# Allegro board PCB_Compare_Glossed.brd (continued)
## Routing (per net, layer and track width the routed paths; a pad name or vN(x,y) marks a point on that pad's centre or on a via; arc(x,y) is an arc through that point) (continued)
RA8: length 166.3
  TOP w0.127: v1(106.17,77.39) 106.17,82.17 106.68,82.68 U16.28 ; U11.28 106.68,105.33 107.31,104.7 107.31,99.06 106.68,98.42 U17.28 v1(106.68,94.72) ; 59.18,87 v1(59.72,86.46) ; v1(81.91,81.48) U14.28 81.91,85.85 81.28,86.49 81.28,89.97 81.91,90.6 U13.28 81.91,98.37 82.55,99.01 82.55,105.66 81.91,106.3 U15.28 ; U12.28 106.68,69.52 v1(107.7,68.5) ; U10.28 81.91,67.26 v1(81.41,66.75)
  INNER_1 w0.127: v1(107.7,68.5) 106.17,70.03 v1(106.17,77.39) 106.68,77.9 v1(106.68,94.72) ; v1(81.91,81.48) 81.91,67.26 v1(81.41,66.75)
  INNER_2 w0.127: v1(81.91,81.48) 82.63,80.77 83.44,80.77 83.69,80.52 83.69,80.01 82.93,79.25 61.14,79.25 57.94,82.45 57.94,85.42 58.45,85.93 59.18,85.93 v1(59.72,86.46) ; v1(81.41,66.75) 81.91,67.26 106.45,67.26 v1(107.7,68.5)
RA9: length 158.6
  TOP w0.127: U14.22 89.53,79.78 v1(90.3,79.02) ; U10.22 89.53,72.19 v1(88.27,73.46) ; U13.22 89.53,98.37 88.9,99.01 88.9,101.4 88.95,101.45 v1(88.95,102.31) 89.53,102.9 U15.22 89.53,111 89.66,111.12 114.17,111.12 114.3,111 U11.22 114.3,107.14 113.66,106.5 113.66,99.01 114.3,98.37 U17.22 114.3,94.69 113.66,94.06 113.66,86.31 114.3,85.67 U16.22 114.3,77.93 113.66,77.29 113.66,73.61 114.3,72.97 U12.22 ; U5.E8 v1(58.45,88.8)
  BOTTOM w0.127: v1(88.95,102.31) 89.1,102.16 89.1,80.21 v1(90.3,79.02) 90.3,75.49 v1(88.27,73.46) 68.1,73.46 58.95,82.6 58.95,88.29 v1(58.45,88.8)
RA10: length 147
  TOP w0.127: v1(91.31,66.75) 90.81,67.26 U10.21 90.81,73.1 91.44,73.74 91.44,76.07 91.31,76.2 91.31,80.39 90.81,80.9 U14.21 90.81,85.7 90.17,86.33 v1(90.17,89.41) 91.31,90.55 91.31,93.78 90.81,94.28 U13.21 90.81,98.63 91.44,99.26 91.44,104.72 90.81,105.36 U15.21 ; U5.E9 v1(59.72,88.8) ; v1(115.93,66.75) 115.57,67.11 U12.21 115.57,72.97 114.94,73.61 114.94,76.02 115.57,76.66 U16.21 115.57,85.67 114.94,86.31 114.94,90.5 115.57,91.14 U17.21 115.57,98.65 116.21,99.29 116.21,104.72 115.57,105.36 U11.21
  INNER_2 w0.127: v1(90.17,89.41) 88.57,87.81 60.71,87.81 v1(59.72,88.8)
  BOTTOM w0.127: v1(115.93,66.75) v1(91.31,66.75)
RA11: length 171.8
  TOP w0.127: U5.E10 v1(60.99,88.8) ; v1(91.82,79.27) 92.07,79.53 U14.20 92.07,85.67 91.44,86.31 91.44,88.77 91.57,88.9 91.57,90.88 92.07,91.39 U13.20 92.07,98.37 92.58,98.88 92.58,104.85 92.07,105.36 U15.20 ; U10.20 92.07,66.24 v1(91.82,65.99) ; U11.20 116.84,105.36 117.35,104.85 117.35,99.14 116.84,98.63 U17.20 116.84,91.39 117.35,90.88 117.35,86.18 116.84,85.67 U16.20 116.84,76.66 116.21,76.02 116.21,73.61 116.84,72.97 U12.20 v1(116.84,69.8)
  INNER_1 w0.127: v1(91.82,65.99) v1(91.82,79.27)
  INNER_2 w0.127: v1(91.82,65.99) 113.03,65.99 v1(116.84,69.8)
  BOTTOM w0.127: v1(60.99,88.8) 60.48,89.31 58.19,89.31 57.94,89.05 57.94,82.35 67.34,72.95 88.52,72.95 91.82,76.25 v1(91.82,79.27)
RA12: length 165.7
  TOP w0.127: v1(93.34,70.31) 93.34,72.77 92.71,73.41 92.71,81.51 93.34,82.14 93.34,85.93 93.85,86.44 93.85,90.68 93.34,91.19 93.34,97.16 92.84,97.66 92.84,107.92 93.34,108.43 93.34,109.86 ; U11.19 118.11,108.56 117.6,108.05 117.6,98.88 118.11,98.37 U17.19 118.11,94.18 117.6,93.68 117.6,86.18 118.11,85.67 U16.19 118.11,82.83 117.47,82.19 117.47,73.61 118.11,72.97 U12.19 118.11,70.36 v1(117.63,69.88) ; U5.G2 v1(49.76,85.19)
  INNER_2 w0.127: v1(117.63,69.88) 116.18,71.32 94.36,71.32 v1(93.34,70.31) 88.67,74.98 50.65,74.98 49.12,76.5 49.12,80.04 51.54,82.45 51.54,83.41 v1(49.76,85.19)
RA13: length 154.7
  TOP w0.127: 50.29,87 v1(49.76,86.46) ; U15.18 94.62,108.43 95.25,107.8 95.25,99.01 94.62,98.37 U13.18 94.62,91.21 94.11,90.7 94.11,86.18 94.62,85.67 U14.18 94.62,81.38 v1(93.34,80.11) 93.98,79.48 93.98,73.61 94.62,72.97 U10.18 ; U12.18 119.38,72.97 118.75,73.61 118.75,79.91 v1(119.38,80.54) U16.18 119.38,85.67 118.75,86.31 118.75,88.77 118.87,88.9 118.87,95.43 119.38,95.94 U17.18 119.38,98.6 118.75,99.24 118.75,106.02 119.38,106.65 U11.18
  INNER_2 w0.127: v1(49.76,86.46) 51.79,84.43 51.79,83.67 52.04,83.41 57.15,83.41 57.68,82.88 57.68,82.3 60.99,78.99 83.82,78.99 84.94,80.11 v1(93.34,80.11) 118.95,80.11 v1(119.38,80.54)
RA14: length 164.5
  TOP w0.127: U10.15 94.62,65.2 95.25,65.84 95.25,72.85 94.62,73.48 U14.15 94.62,79.12 95.25,79.76 95.25,85.55 94.62,86.18 U13.15 94.62,90.22 v1(95.88,91.49) ; U12.15 119.38,63.45 120.01,64.08 120.01,72.85 119.38,73.48 U16.15 119.38,77.93 120.01,78.56 120.01,85.57 119.38,86.21 U17.15 119.38,91.9 120.01,92.53 120.01,98.37 119.38,99.01 U11.15 v1(119.38,104.14) ; U15.15 v1(94.62,104.01) ; U5.E2 v1(49.76,88.8)
  INNER_1 w0.127: v1(94.62,104.01) 94.74,104.14 v1(119.38,104.14)
  INNER_2 w0.127: v1(49.76,88.8) 50.52,89.56 51.26,89.56 53.04,91.34 53.04,91.57 53.57,92.1 95.28,92.1 v1(95.88,91.49)
  BOTTOM w0.127: v1(95.88,91.49) 94.62,92.76 v1(94.62,104.01)
RA15: length 163.7
  TOP w0.127: 93.34,100.33 v1(93.34,98.68) ; 93.34,87.63 93.34,86.69 v1(92.84,86.18) ; U11.14 118.11,98.96 118.75,98.32 118.75,96.01 118.62,95.89 118.62,93.42 118.11,92.91 U17.14 118.11,86.18 118.75,85.55 118.75,82.19 118.11,81.56 U16.14 118.11,73.48 118.75,72.85 118.75,64.36 118.11,63.73 U12.14 v1(118.11,60.71) ; v1(93.34,60.32) 93.34,64.64 93.98,65.28 93.98,72.9 93.34,73.53 v1(93.34,79.38) ; U5.D2 v1(49.76,90.07)
  INNER_1 w0.127: v1(92.84,86.18) 92.84,79.88 v1(93.34,79.38) ; v1(118.11,60.71) 117.35,59.94 93.73,59.94 v1(93.34,60.32) ; v1(49.76,90.07) 50.52,90.83 54.23,90.83 56.52,93.12 63.27,93.12 76.99,106.83 85.19,106.83 v1(93.34,98.68)
  BOTTOM w0.127: v1(92.84,86.18) 92.84,98.17 v1(93.34,98.68)
RCS0: length 44.9
  TOP w0.127: v1(83.19,80.26) 83.19,73.66 82.68,73.15 82.68,67.77 83.19,67.26 83.19,62.23 ; U5.J8 v1(58.45,82.65)
  INNER_2 w0.127: v1(83.19,80.26) 60.83,80.26 v1(58.45,82.65)
RCS1: length 66.5
  TOP w0.127: 83.19,100.33 v1(83.19,101.78) ; U5.J9 v1(59.72,82.65) ; U11.6 v1(107.95,101.78)
  INNER_2 w0.127: v1(107.95,101.78) 107.19,101.02 83.95,101.02 v1(83.19,101.78)
  BOTTOM w0.127: v1(83.19,101.78) 81.41,100 81.41,89.59 75.23,83.41 60.48,83.41 v1(59.72,82.65)
RCS2: length 68.4
  TOP w0.127: v1(107.95,80.62) U16.6 107.95,73.48 108.59,72.85 108.59,66.6 107.95,65.96 U12.6 ; U5.J10 v1(60.99,82.65)
  INNER_2 w0.127: v1(107.95,80.62) 106.93,81.64 82.6,81.64 82.25,81.99 81.64,81.99 80.52,80.87 62.76,80.87 v1(60.99,82.65)
RCS3: length 62.3
  TOP w0.127: 51.56,87 v1(51.03,86.46) ; U17.6 v1(107.95,89.08) ; 83.19,87.63 v1(83.19,89.08)
  GND w0.127: v1(83.19,89.08) 81.36,87.25 51.82,87.25 v1(51.03,86.46)
  INNER_2 w0.127: v1(83.19,89.08) 84.02,89.92 91.29,89.92 92.13,89.08 v1(107.95,89.08)
RD0: length 111
  TOP w0.127: U15.26 v1(84.45,108.41) ; U14.26 v1(84.45,83.01) ; v1(109.22,82.04) U16.26 109.22,85.67 109.85,86.31 109.85,90.35 109.22,90.98 U17.26 ; 49.02,87 v1(48.49,86.46)
  GND w0.127: v1(84.45,83.01) 81.2,79.76 65.05,79.76 61.39,83.41 58.19,83.41 57.94,83.67 57.94,83.92 57.18,84.68 49.5,84.68 49.25,84.94 49.25,85.7 v1(48.49,86.46)
  INNER_2 w0.127: v1(84.45,83.01) 85.42,82.04 v1(109.22,82.04)
  BOTTOM w0.127: v1(84.45,108.41) 83.95,107.9 83.95,83.52 v1(84.45,83.01)
RD1: length 116.8
  TOP w0.127: U15.23 v1(88.27,108.41) ; v1(113.03,82.3) U16.23 113.03,85.67 112.4,86.31 112.4,90.42 113.03,91.06 U17.23 ; U5.E1 v1(48.49,88.8) ; U14.23 v1(88.27,83.01)
  INNER_1 w0.127: v1(82.93,85.9) 81.41,87.43 81.41,90.07 79.63,91.85 57.99,91.85 55.45,89.31 49,89.31 v1(48.49,88.8)
  INNER_2 w0.127: v1(113.03,82.3) 110.19,82.3 108.71,83.77 89.03,83.77 v1(88.27,83.01) 85.37,85.9 v1(82.93,85.9)
  BOTTOM w0.127: v1(88.27,83.01) 87.76,83.52 87.76,107.9 v1(88.27,108.41)
RD2: length 113.3
  TOP w0.127: U16.10 113.03,78.16 v1(112.67,78.51) 113.66,79.5 113.66,85.55 113.03,86.18 U17.10 ; U14.10 v1(88.27,76.38) ; U15.10 v1(88.27,101.78) ; U5.D1 v1(48.49,90.07)
  INNER_1 w0.127: v1(48.49,90.07) 49,89.56 55.09,89.56 57.63,92.1 78.59,92.1 v1(88.27,101.78)
  INNER_2 w0.127: v1(88.27,76.38) 109.09,76.38 111.23,78.51 v1(112.67,78.51)
  BOTTOM w0.127: v1(88.27,76.38) 88.77,76.89 88.77,101.27 v1(88.27,101.78)
RD3: length 107.5
  TOP w0.127: U14.7 v1(84.45,76.38) ; U16.7 109.22,78.16 v1(108.86,78.51) 108.59,78.79 108.59,85.55 109.22,86.18 U17.7 ; U5.H1 v1(48.49,83.92) ; U15.7 v1(84.45,101.78)
  GND w0.127: v1(48.49,83.92) 49,84.43 54.56,84.43 60.99,78 82.83,78 v1(84.45,76.38)
  INNER_2 w0.127: v1(84.45,76.38) 86.59,78.51 v1(108.86,78.51)
  BOTTOM w0.127: v1(84.45,101.78) 84.96,101.27 84.96,76.89 v1(84.45,76.38)
RD4: length 128.8
  TOP w0.127: U12.26 v1(109.22,70.31) ; U11.26 v1(109.22,108.41) ; U5.A1 v1(48.49,93.88) ; U10.26 v1(84.45,70.31) ; U13.26 v1(84.45,95.71)
  INNER_1 w0.127: v1(84.45,70.31) 83.95,70.82 83.95,95.2 v1(84.45,95.71)
  INNER_2 w0.127: v1(48.49,93.88) 51.08,96.47 83.69,96.47 v1(84.45,95.71) 87.93,99.19 106.17,99.19 108.71,101.73 108.71,107.9 v1(109.22,108.41) ; v1(84.45,70.31) 85.27,69.49 108.41,69.49 v1(109.22,70.31)
RD5: length 131
  TOP w0.127: U13.23 v1(88.27,95.71) ; U12.23 v1(113.03,70.31) ; U10.23 v1(88.27,70.31) ; U5.A2 v1(49.76,93.88) ; U11.23 v1(113.03,108.41)
  INNER_1 w0.127: v1(88.27,70.31) 87.76,70.82 87.76,95.2 v1(88.27,95.71)
  INNER_2 w0.127: v1(113.03,108.41) 112.52,107.9 112.52,101.8 106.93,96.22 88.77,96.22 v1(88.27,95.71) 87.3,94.74 50.62,94.74 v1(49.76,93.88) ; v1(113.03,70.31) 112.27,71.07 96.77,71.07 95.5,69.8 88.77,69.8 v1(88.27,70.31)
RD6: length 128.5
  TOP w0.127: U13.10 v1(88.27,89.08) ; U5.A3 v1(51.03,93.88) ; U10.10 v1(88.27,63.68) ; U12.10 v1(113.03,63.68) ; U11.10 v1(113.03,101.78)
  GND w0.127: 88.27,94.13 87.99,94.41 51.56,94.41 v1(51.03,93.88) ; 88.27,94.13 v1(88.27,89.08) ; 88.27,94.13 105.38,94.13 v1(113.03,101.78)
  INNER_1 w0.127: v1(88.27,63.68) 89.03,64.44 89.03,88.32 v1(88.27,89.08)
  INNER_2 w0.127: v1(113.03,63.68) 112.27,62.92 89.03,62.92 v1(88.27,63.68)
RD7: length 124.4
  TOP w0.127: U11.7 v1(109.22,101.78) ; U13.7 v1(84.45,89.08) ; U5.A4 v1(52.3,93.88) ; U12.7 v1(109.22,63.68) ; U10.7 v1(84.45,63.68)
  INNER_1 w0.127: v1(84.45,89.08) 84.96,88.57 84.96,64.19 v1(84.45,63.68)
  INNER_2 w0.127: v1(109.22,63.68) 107.7,65.2 85.98,65.2 v1(84.45,63.68)
  VCC w0.127: 84.45,93.34 84.45,93.8 85.17,94.51 85.17,95.96 86.44,97.23 104.67,97.23 v1(109.22,101.78) ; 84.45,93.34 v1(84.45,89.08) ; 84.45,93.34 U5.A4 v1(52.3,93.88)
RDY: length 39.9
  INNER_2 w0.127: J1.50 14.48,62.74 38.84,62.74 47.62,53.95 U2.23
RESET: length 72.4
  TOP w0.127: U5.B5 v1(53.57,92.61)
  BOTTOM w0.127: v1(53.57,92.61) 53.06,93.12 53.06,93.83 45.92,100.97 22.1,100.97 16.48,95.35 16.48,72.36 J1.53
RWE: length 151.1
  TOP w0.127: U5.H5 v1(53.57,83.92) ; U11.11 114.3,98.88 114.94,98.25 114.94,93.29 114.3,92.66 U17.11 114.3,86.18 114.94,85.55 114.94,77.29 114.3,76.66 U16.11 114.3,73.36 114.91,72.75 114.91,64.11 114.3,63.5 U12.11 114.3,61.72 112.27,59.69 90.17,59.69 89.53,60.32 U10.11 89.53,63.45 90.17,64.08 90.17,73 89.53,73.63 U14.11 89.53,77.17 88.9,77.8 88.9,85.55 89.53,86.18 U13.11 89.53,90.47 v1(90.55,91.49) 90.17,91.87 90.17,98.25 89.53,98.88 U15.11
  INNER_2 w0.127: v1(90.55,91.49) 90.2,91.85 58.14,91.85 53.57,87.27 v1(53.57,83.92)
SEL: length 66.8
  TOP w0.127: U5.B3 v1(51.03,92.61)
  INNER_1 w0.127: U2.14 45.97,32.13 45.97,89.56 48.51,92.1 50.52,92.1 v1(51.03,92.61)
V+12: length 200.6
  TOP w0.203: 71.88,36.2 90.3,36.2
  TOP w0.381: U20.7 104.78,20.32 v1(104.32,20.32) U23.4 ; 71.88,36.2 70.36,36.2 69.09,37.46 69.09,89.31 59.97,98.42 14.6,98.42 J1.64 J1.63 ; 90.3,36.2 95.25,36.2 95.88,36.83 107.31,36.83 ; U19.4 v1(104.32,40)
  INNER_1 w0.381: v1(102.62,27.3) 104.32,25.6 v1(104.32,20.32)
  INNER_2 w0.381: v1(104.32,40) 104.32,39.83 107.31,36.83
  BOTTOM w0.381: C28.1 v1(102.62,8.25) 103.35,8.99 103.35,19.35 v1(104.32,20.32) ; 107.31,36.83 102.62,32.13 v1(102.62,27.3) C25.1
VCLKA: length 86.8
  TOP w0.203: U5.J4 v1(52.3,82.65) ; U21.11 v1(78.26,20.32) ; U8.11 v1(74.78,29.21) ; U18.11 v1(77.62,40.64)
  INNER_1 w0.203: v1(52.3,82.65) 52.3,55.22 64.49,43.03 75.23,43.03 v1(77.62,40.64) 74.78,37.8 v1(74.78,29.21) 78.26,25.73 v1(78.26,20.32)
VCLKC: length 90.1
  TOP w0.127: U9.11 v1(71.86,8.89)
  INNER_1 w0.127: v1(45.08,77.47) 45.08,22.35 57.78,9.65 71.09,9.65 v1(71.86,8.89)
  BOTTOM w0.127: R5.2 v1(45.08,77.47)
VD0: length 103.2
  TOP w0.127: U5.K2 50.29,75.06 66.42,58.93 66.42,56.77 65.53,55.88 U6.2 62.74,55.88 60.83,53.98 60.83,44.32 62.36,42.8 64.39,42.8 66.17,41.02 66.17,40 65.53,39.37 U8.2 62.81,39.37 60.71,37.26 60.71,27.05 63.25,24.51 64.77,24.51 66.67,22.61 66.67,20.19 65.53,19.05 U9.2 52.45,19.05 v1(49.91,21.59)
  BOTTOM w0.127: R9.2 v1(49.91,21.59)
VD1: length 103.5
  TOP w0.127: v1(49.78,19.05) 51.05,17.78 U9.3 65.53,17.78 66.93,19.18 66.93,22.73 64.9,24.77 63.37,24.77 60.96,27.18 60.96,36.25 62.81,38.1 U8.3 65.53,38.1 66.42,38.99 66.42,41.15 64.52,43.05 62.48,43.05 61.09,44.45 61.09,52.83 62.87,54.61 U6.3 65.53,54.61 66.67,55.75 66.67,59.05 51.56,74.17 U5.K3
  BOTTOM w0.127: R13.2 v1(49.78,19.05)
VD2: length 103.9
  TOP w0.127: v1(49.78,16.51) U9.4 65.53,16.51 67.18,18.16 67.18,22.86 65.02,25.02 63.5,25.02 61.21,27.3 61.21,35.23 62.81,36.83 U8.4 65.53,36.83 66.67,37.97 66.67,41.27 64.64,43.31 62.61,43.31 61.34,44.58 61.34,51.82 62.87,53.34 U6.4 65.53,53.34 66.93,54.74 66.93,59.18 52.83,73.28 U5.K4
  BOTTOM w0.127: R8.2 v1(49.78,16.51)
VD3: length 105.4
  TOP w0.127: U5.K5 54.1,72.39 67.18,59.31 67.18,53.72 65.53,52.07 U6.5 62.87,52.07 61.59,50.8 61.59,44.7 62.74,43.56 64.77,43.56 66.93,41.4 66.93,36.96 65.53,35.56 U8.5 62.87,35.56 61.47,34.16 61.47,27.43 63.63,25.27 65.15,25.27 67.44,22.99 67.44,17.14 65.53,15.24 U9.5 51.18,15.24 v1(49.91,13.97)
  BOTTOM w0.127: R12.2 v1(49.91,13.97)
VD4: length 106.9
  TOP w0.127: v1(49.78,11.43) 52.32,13.97 U9.6 65.53,13.97 67.69,16.13 67.69,23.11 65.28,25.53 63.75,25.53 61.72,27.56 61.72,33.15 62.87,34.29 U8.6 65.53,34.29 67.18,35.94 67.18,41.53 64.9,43.81 62.87,43.81 61.85,44.83 61.85,49.78 62.87,50.8 U6.6 65.53,50.8 67.44,52.7 67.44,59.44 55.37,71.5 U5.K6
  BOTTOM w0.127: R7.2 v1(49.78,11.43)
VD5: length 108.4
  TOP w0.127: v1(49.78,8.89) 53.59,12.7 U9.7 65.53,12.7 67.94,15.11 67.94,23.24 65.41,25.78 63.88,25.78 61.98,27.69 61.98,32.13 62.87,33.02 U8.7 65.53,33.02 67.44,34.92 67.44,41.66 65.02,44.07 62.99,44.07 62.1,44.96 62.1,48.77 62.87,49.53 U6.7 65.53,49.53 67.69,51.69 67.69,59.56 56.64,70.61 U5.K7
  BOTTOM w0.127: R11.2 v1(49.78,8.89)
VD6: length 109.9
  TOP w0.127: U5.K8 57.91,69.72 67.94,59.69 67.94,50.67 65.53,48.26 U6.8 62.87,48.26 62.36,47.75 62.36,45.09 63.12,44.32 65.15,44.32 67.69,41.78 67.69,33.91 65.53,31.75 U8.8 62.74,31.75 62.23,31.24 62.23,27.81 64.01,26.03 65.53,26.03 68.2,23.37 68.2,14.1 65.53,11.43 U9.8 54.86,11.43 v1(49.78,6.35)
  BOTTOM w0.127: R6.2 v1(49.78,6.35)
VD7: length 111.2
  TOP w0.127: v1(49.78,3.81) 56.13,10.16 U9.9 65.53,10.16 68.45,13.08 68.45,23.49 65.66,26.29 64.13,26.29 62.48,27.94 62.48,30.1 62.87,30.48 U8.9 65.53,30.48 67.94,32.89 67.94,41.91 65.28,44.58 63.25,44.58 62.61,45.21 62.61,46.61 62.99,46.99 U6.9 65.53,46.99 68.2,49.66 68.2,59.82 59.18,68.83 U5.K9
  BOTTOM w0.127: R10.2 v1(49.78,3.81)
VREF: length 35.3
  TOP w0.127: R14.1 v1(101.98,5.08) 103.56,6.65 112.73,6.65 L5.1
  INNER_1 w0.127: L3.1 115.16,23.27 115.16,5.94 L5.1
WAIT: length 47
  TOP w0.127: U5.J3 v1(51.03,82.65)
  INNER_2 w0.127: v1(51.03,82.65) 31.88,63.5 J1.51
WSTAT: length 54.8
  TOP w0.127: U5.H4 v1(52.3,83.92) ; U6.11 v1(74.78,45.72)
  INNER_1 w0.127: v1(52.3,83.92) 52.86,83.36 52.86,58.93 65.56,46.23 74.27,46.23 v1(74.78,45.72)
N00036: length 35.6
  TOP w0.127: U18.8 v1(89.71,38.1) 91.62,40 v1(96.44,40) U19.5 ; v1(101.45,30.48) 103.99,27.94 L4.2 ; U18.5 v1(89.71,34.29)
  INNER_1 w0.127: v1(89.71,38.1) 90.22,37.59 90.22,34.8 v1(89.71,34.29) ; v1(96.44,40) 101.45,35 v1(101.45,33.02) v1(101.45,30.48)
  BOTTOM w0.127: R16.1 v1(101.45,33.02) ; R15.1 v1(101.45,30.48)
N00038: length 29.2
  TOP w0.127: U18.4 v1(89.71,33.02)
  INNER_2 w0.127: v1(83.82,31.55) 85.29,33.02 v1(89.71,33.02) 97.97,24.77 L3.2
  BOTTOM w0.127: C24.1 v1(83.82,31.55)
N00044: length 36.8
  TOP w0.127: U19.1 v1(104.32,36.2)
  INNER_1 w0.127: U20.2 112.29,14.25 108.36,10.31 106.48,10.31 104.83,11.96 104.83,35.69 v1(104.32,36.2)
N00060: length 37.4
  TOP w0.127: U18.6 v1(89.71,35.56)
  INNER_2 w0.127: v1(89.71,35.56) 102.84,35.56 106.91,31.5 106.91,30.12 113.28,23.75 113.28,17.4 U20.3
N14843: length 3.2
  BOTTOM w0.127: C13.1 R12.1
N14849: length 3.2
  BOTTOM w0.127: C9.1 R8.1
N14853: length 3.2
  BOTTOM w0.127: C14.1 R13.1
N14855: length 4.4
  BOTTOM w0.127: C10.1 43.87,21.59 43.99,21.72 43.99,22.23 44.12,22.35 44.37,22.35 44.5,22.23 44.5,21.72 44.63,21.59 R9.1
N15143: length 3.2
  BOTTOM w0.127: C11.1 R10.1
N15151: length 3.2
  BOTTOM w0.127: C7.1 R6.1
N15155: length 3.2
  BOTTOM w0.127: C12.1 R11.1
N15161: length 3.2
  BOTTOM w0.127: C8.1 R7.1
N58063: length 5.7
  TOP w0.127: U8.19 U18.12
N58118: length 5.7
  TOP w0.127: U8.18 U18.13
N58173: length 5.7
  TOP w0.127: U8.17 U18.14
N58228: length 5.7
  TOP w0.127: U8.16 U18.15
N58283: length 5.7
  TOP w0.127: U8.15 U18.16
N58338: length 5.7
  TOP w0.127: U8.14 U18.17
N58393: length 5.7
  TOP w0.127: U8.13 U18.18
N58448: length 5.7
  TOP w0.127: U8.12 U18.19
N58834: length 6.4
  TOP w0.127: U9.19 U21.12
N58889: length 6.4
  TOP w0.127: U9.18 U21.13
N58944: length 6.4
  TOP w0.127: U9.17 U21.14
N58999: length 6.4
  TOP w0.127: U9.16 U21.15
N59054: length 6.4
  TOP w0.127: U9.15 U21.16
N59109: length 6.4
  TOP w0.127: U9.14 U21.17
N59164: length 6.4
  TOP w0.127: U9.13 U21.18
N59219: length 6.4
  TOP w0.127: U9.12 U21.19
N282866: length 6
  TOP w0.127: U19.8 v1(96.44,36.2)
  INNER_1 w0.127: v1(96.44,36.2) 96.9,35.74 v1(96.9,33.02)
  BOTTOM w0.127: R16.2 v1(96.9,33.02)
N282912: length 13.7
  TOP w0.127: U19.2 v1(104.32,37.46)
  BOTTOM w0.127: v1(104.32,37.46) 103,37.46 99.19,33.66 99.19,32.33 97.33,30.48 v1(96.9,30.48) R15.2
N409523: length 11.5
  TOP w0.127: v1(57.15,82.63) 57.15,82.68 U5.J7
  INNER_2 w0.127: v1(57.15,82.63) 51.99,77.47 v1(49.68,77.47)
  BOTTOM w0.127: R5.1 v1(49.68,77.47)

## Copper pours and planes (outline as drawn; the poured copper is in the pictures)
GND on GND: 23.44,1.37 22.96,1.85 22.96,6.45 1.85,6.45 1.37,6.93 1.37,107.37 1.85,107.85 22.96,107.85 22.96,112.45 23.44,112.93 123.88,112.93 124.36,112.45 124.36,1.85 123.88,1.37
V12N on VCC: 115.77,1.37 115.77,14.94 114.63,16.05 111.84,16.05 106.12,21.79 100.89,21.79 100.13,21.03 100.13,17.22 99.62,16.71 95.96,16.71 95.45,17.22 95.45,25.07 95.96,25.6 103.96,25.6 104.6,26.21 104.6,28.27 103.96,28.91 95.83,28.91 95.45,29.29 95.45,37.39 95.96,37.9 97.08,37.9 97.59,37.39 97.59,35.48 98.35,34.75 109.3,34.75 110.03,35.48 110.03,41.1 113.59,41.1 114.76,39.93 114.76,30.56 114.22,30.02 112.95,30.02 112.22,29.29 112.22,26.59 112.95,25.86 124.36,25.86 124.36,1.85 123.88,1.37
VCC on VCC: 23.44,1.37 22.96,1.85 22.96,6.45 1.85,6.45 1.37,6.93 1.37,107.37 1.85,107.85 22.96,107.85 22.96,112.45 23.44,112.93 123.88,112.93 124.36,112.45 124.36,26.21 113.11,26.21 112.57,26.75 112.57,29.13 113.11,29.67 114.38,29.67 115.11,30.4 115.11,40.08 113.74,41.45 93.27,41.45 92.51,40.72 92.51,10.72 95.81,7.42 103.58,7.42 105.49,9.35 115.37,9.35 115.37,1.37
V+12 on VCC: 95.96,7.82 92.91,10.87 92.91,40.56 93.42,41.1 109.68,41.1 109.68,35.64 109.14,35.1 98.5,35.1 97.99,35.64 97.99,37.54 97.23,38.3 95.81,38.3 95.05,37.54 95.05,29.13 95.68,28.5 103.81,28.5 104.19,28.12 104.19,26.37 103.81,25.96 95.81,25.96 95.05,25.22 95.05,17.07 95.81,16.31 99.77,16.31 100.53,17.07 100.53,20.88 101.04,21.39 105.97,21.39 111.68,15.7 114.48,15.7 115.37,14.78 115.37,9.7 105.33,9.7 103.43,7.82

Small or netless copper shapes (teardrops, artwork), in the pictures only: 918 on TOP, 174 on BOTTOM, 18 on GND, 133 on INNER_1, 134 on INNER_2, 14 on VCC

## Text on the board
XSECTION_CHART: *  SURFACE - AIR 0 MIL | L1: TOP CONDUCTOR - COPPER 1 MIL | *  DIELECTRIC - FR-4 8 MIL | L2: GND PLANE - COPPER 1 MIL | L3: INNER_1 CONDUCTOR - COPPER 1 MIL | L4: INNER_2 CONDUCTOR - COPPER 1 MIL | L5: VCC PLANE - COPPER 1 MIL | L6: BOTTOM CONDUCTOR - COPPER 1 MIL | DESIGN CROSS SECTION CHART | ___________________________ | TOTAL THICKNESS 46 MIL | 1-6 | FIGURE | SIZE | 13.0 | 31.0 | 38.0 | 75.0 | 110.0 | DRILL CHART: TOP to BOTTOM | ALL UNITS ARE IN MILS | PLATED | NON-PLATED | QTY | 492 | 12 | 122 | 8 | 5
